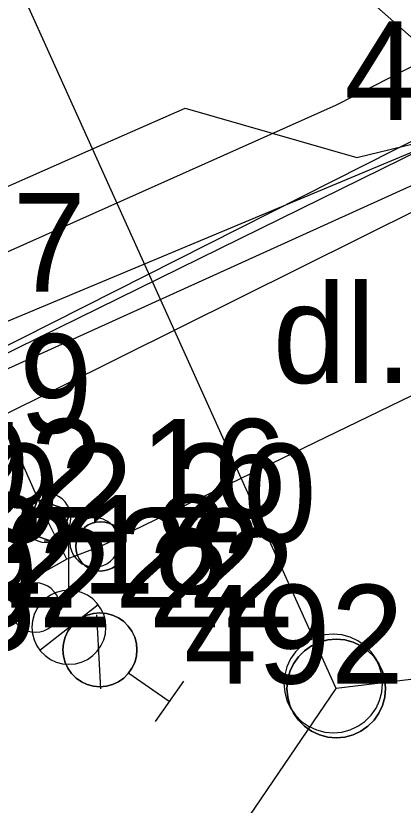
# Model space of a CAD drawing. Extents: x -695326 to -694942, y -1122979 to -1122738.
# Drawn here: x -694975.72 to -694971.79, y -1122884 to -1122876 of the extents above; entities that cross this region are included whole.
import ezdxf

# ---------------------------------------------------------------- set-up
doc = ezdxf.new("R2010")
doc.units = 0
for name, color, linetype in [('Level 29', 7, 'Continuous'), ('Level 30', 7, 'Continuous'), ('Level 35', 7, 'Continuous'), ('Level 36', 7, 'Continuous'), ('Level 37', 7, 'Continuous'), ('Level 38', 7, 'Continuous'), ('Level 44', 7, 'Continuous'), ('Level 51', 7, 'Continuous'), ('Level 53', 7, 'Continuous'), ('Popisy', 7, 'Continuous'), ('Rozhraní ploch', 7, 'Continuous'), ('trasa_man_Mesto', 7, 'Continuous')]:
    doc.layers.add(name, color=color, linetype=linetype)

msp = doc.modelspace()

# ---------------------------------------------------------------- linework, layer by layer
at = {"layer": 'Level 29'}
for p, q in [((-694975.41, -1122881.09), (-694975.41, -1122881.09)), ((-694974.92, -1122881.34), (-694974.92, -1122881.34)), ((-694975.52, -1122882), (-694975.52, -1122882)), ((-694975.18, -1122882.2), (-694975.18, -1122882.2))]:
    msp.add_line(p, q, dxfattribs=at)
for points in [[(-694975.16, -1122881.09), (-694975.1638, -1122881.0466), (-694975.1751, -1122881.0045), (-694975.1935, -1122880.965), (-694975.2185, -1122880.9293), (-694975.2493, -1122880.8985), (-694975.285, -1122880.8735), (-694975.3245, -1122880.8551), (-694975.3666, -1122880.8438), (-694975.41, -1122880.84), (-694975.4534, -1122880.8438), (-694975.4955, -1122880.8551), (-694975.535, -1122880.8735), (-694975.5707, -1122880.8985), (-694975.6015, -1122880.9293), (-694975.6265, -1122880.965), (-694975.6449, -1122881.0045), (-694975.6562, -1122881.0466), (-694975.66, -1122881.09), (-694975.6562, -1122881.1334), (-694975.6449, -1122881.1755), (-694975.6265, -1122881.215), (-694975.6015, -1122881.2507), (-694975.5707, -1122881.2815), (-694975.535, -1122881.3065), (-694975.4955, -1122881.3249), (-694975.4534, -1122881.3362), (-694975.41, -1122881.34), (-694975.3666, -1122881.3362), (-694975.3245, -1122881.3249), (-694975.285, -1122881.3065), (-694975.2493, -1122881.2815), (-694975.2185, -1122881.2507), (-694975.1935, -1122881.215), (-694975.1751, -1122881.1755), (-694975.1638, -1122881.1334), (-694975.16, -1122881.09)], [(-694974.67, -1122881.34), (-694974.6738, -1122881.2966), (-694974.6851, -1122881.2545), (-694974.7035, -1122881.215), (-694974.7285, -1122881.1793), (-694974.7593, -1122881.1485), (-694974.795, -1122881.1235), (-694974.8345, -1122881.1051), (-694974.8766, -1122881.0938), (-694974.92, -1122881.09), (-694974.9634, -1122881.0938), (-694975.0055, -1122881.1051), (-694975.045, -1122881.1235), (-694975.0807, -1122881.1485), (-694975.1115, -1122881.1793), (-694975.1365, -1122881.215), (-694975.1549, -1122881.2545), (-694975.1662, -1122881.2966), (-694975.17, -1122881.34), (-694975.1662, -1122881.3834), (-694975.1549, -1122881.4255), (-694975.1365, -1122881.465), (-694975.1115, -1122881.5007), (-694975.0807, -1122881.5315), (-694975.045, -1122881.5565), (-694975.0055, -1122881.5749), (-694974.9634, -1122881.5862), (-694974.92, -1122881.59), (-694974.8766, -1122881.5862), (-694974.8345, -1122881.5749), (-694974.795, -1122881.5565), (-694974.7593, -1122881.5315), (-694974.7285, -1122881.5007), (-694974.7035, -1122881.465), (-694974.6851, -1122881.4255), (-694974.6738, -1122881.3834), (-694974.67, -1122881.34)], [(-694975.43, -1122881.325), (-694974.93, -1122881.325)], [(-694975.18, -1122881.825), (-694975.18, -1122881.325)], [(-694975.27, -1122882), (-694975.2738, -1122881.9566), (-694975.2851, -1122881.9145), (-694975.3035, -1122881.875), (-694975.3285, -1122881.8393), (-694975.3593, -1122881.8085), (-694975.395, -1122881.7835), (-694975.4345, -1122881.7651), (-694975.4766, -1122881.7538), (-694975.52, -1122881.75), (-694975.5634, -1122881.7538), (-694975.6055, -1122881.7651), (-694975.645, -1122881.7835), (-694975.6807, -1122881.8085), (-694975.7115, -1122881.8393), (-694975.7365, -1122881.875)], [(-694974.805, -1122882.2), (-694974.8107, -1122882.1349), (-694974.8276, -1122882.0717), (-694974.8552, -1122882.0125), (-694974.8927, -1122881.959), (-694974.939, -1122881.9127), (-694974.9925, -1122881.8752), (-694975.0517, -1122881.8476), (-694975.1149, -1122881.8307), (-694975.18, -1122881.825), (-694975.2451, -1122881.8307), (-694975.3083, -1122881.8476), (-694975.3675, -1122881.8752), (-694975.421, -1122881.9127), (-694975.4673, -1122881.959), (-694975.5048, -1122882.0125), (-694975.5324, -1122882.0717), (-694975.5493, -1122882.1349), (-694975.555, -1122882.2), (-694975.5493, -1122882.2651), (-694975.5324, -1122882.3283), (-694975.5048, -1122882.3875), (-694975.4673, -1122882.441), (-694975.421, -1122882.4873), (-694975.3675, -1122882.5248), (-694975.3083, -1122882.5524), (-694975.2451, -1122882.5693), (-694975.18, -1122882.575), (-694975.1149, -1122882.5693), (-694975.0517, -1122882.5524), (-694974.9925, -1122882.5248), (-694974.939, -1122882.4873), (-694974.8927, -1122882.441), (-694974.8552, -1122882.3875), (-694974.8276, -1122882.3283), (-694974.8107, -1122882.2651), (-694974.805, -1122882.2)], [(-694975.7365, -1122882.125), (-694975.7115, -1122882.1607), (-694975.6807, -1122882.1915), (-694975.645, -1122882.2165), (-694975.6055, -1122882.2349), (-694975.5634, -1122882.2462), (-694975.52, -1122882.25), (-694975.4766, -1122882.2462), (-694975.4345, -1122882.2349), (-694975.395, -1122882.2165), (-694975.3593, -1122882.1915), (-694975.3285, -1122882.1607), (-694975.3035, -1122882.125), (-694975.2851, -1122882.0855), (-694975.2738, -1122882.0434), (-694975.27, -1122882)], [(-694975.474, -1122882.431), (-694974.884, -1122881.968)]]:
    msp.add_lwpolyline(points, dxfattribs=at)
at = {"layer": 'Level 30'}
msp.add_line((-694972.5, -1122882.77), (-694972.5, -1122882.77), dxfattribs=at)
msp.add_lwpolyline([(-694972, -1122882.77), (-694972.0076, -1122882.6832), (-694972.0302, -1122882.599), (-694972.067, -1122882.52), (-694972.117, -1122882.4486), (-694972.1786, -1122882.387), (-694972.25, -1122882.337), (-694972.329, -1122882.3002), (-694972.4132, -1122882.2776), (-694972.5, -1122882.27), (-694972.5868, -1122882.2776), (-694972.671, -1122882.3002), (-694972.75, -1122882.337), (-694972.8214, -1122882.387), (-694972.883, -1122882.4486), (-694972.933, -1122882.52), (-694972.9698, -1122882.599), (-694972.9924, -1122882.6832), (-694973, -1122882.77), (-694972.9924, -1122882.8568), (-694972.9698, -1122882.941), (-694972.933, -1122883.02), (-694972.883, -1122883.0914), (-694972.8214, -1122883.153), (-694972.75, -1122883.203), (-694972.671, -1122883.2398), (-694972.5868, -1122883.2624), (-694972.5, -1122883.27), (-694972.4132, -1122883.2624), (-694972.329, -1122883.2398), (-694972.25, -1122883.203), (-694972.1786, -1122883.153), (-694972.117, -1122883.0914), (-694972.067, -1122883.02), (-694972.0302, -1122882.941), (-694972.0076, -1122882.8568), (-694972, -1122882.77)], dxfattribs=at)
at = {"layer": 'Level 35'}
msp.add_lwpolyline([(-695131.2467, -1122978.8639), (-695132.65, -1122975.94), (-695157.61, -1122969.63), (-695140.47, -1122958.8), (-695136.63, -1122948.53), (-695119.01, -1122943.49), (-695100.79, -1122937.97), (-695082.69, -1122932.49), (-695067.48, -1122925.68), (-695054.28, -1122919.15), (-695039.04, -1122911.54), (-695024.78, -1122904.45), (-695010.56, -1122897.35), (-694996.02, -1122890.13), (-694983.12, -1122883.66), (-694965.65, -1122874.99), (-694952.69, -1122868.61), (-694948.6266, -1122866.5863)], dxfattribs=at)
at = {"layer": 'Level 36'}
for p, q in [((-694960.69, -1122874.53), (-694974.86, -1122881.38)), ((-694975.2, -1122881.51), (-694975.39, -1122881.13)), ((-694974.86, -1122881.38), (-694975.2, -1122881.51))]:
    msp.add_line(p, q, dxfattribs=at)
for points in [[(-694975.39, -1122881.13), (-694982.04, -1122866.09), (-694989.57, -1122849.4), (-694995.06, -1122837.58), (-694995.98, -1122835.83), (-695003.87, -1122820.22)], [(-694976.036, -1122879.197), (-694976, -1122879.18), (-694970.42, -1122876.85), (-694965.1, -1122874.36)], [(-694971.19, -1122876.26), (-694972.47, -1122876.91), (-694977.58, -1122879.19), (-694981.14, -1122881.07), (-694984.99, -1122882.65), (-695001.8, -1122890.18)], [(-694999.83, -1122891.63), (-694989.59, -1122886.52), (-694978.72, -1122881.18), (-694978.15, -1122880.08), (-694977.9, -1122878.66), (-694974.84, -1122877.31), (-694974, -1122876.94), (-694972.26, -1122877.44), (-694970.98, -1122877.13)], [(-694975.2, -1122881.51), (-694975.61, -1122881.74), (-694975.99, -1122881.91)]]:
    msp.add_lwpolyline(points, dxfattribs=at)
at = {"layer": 'Level 37'}
msp.add_lwpolyline([(-695018.76, -1122900.99), (-694999.77, -1122890.98), (-694996.09, -1122889.21), (-694986.68, -1122884.5), (-694984.84, -1122883.53), (-694978.51, -1122880.71), (-694968.71, -1122875.76), (-694963.71, -1122872.9), (-694961.76, -1122871.96), (-694957.17, -1122869.93), (-694955.67, -1122868.8), (-694948.6716, -1122865.3476)], dxfattribs=at)
at = {"layer": 'Level 38'}
for p, q in [((-694972.47, -1122882.82), (-694981.23, -1122863.43)), ((-694959.99, -1122881.29), (-694972.47, -1122882.82)), ((-694974.82, -1122886.27), (-694972.47, -1122882.82))]:
    msp.add_line(p, q, dxfattribs=at)
at = {"layer": 'Level 44'}
for p, q in [((-694975.39, -1122881.13), (-694975.39, -1122881.13)), ((-694974.86, -1122881.38), (-694974.86, -1122881.38)), ((-694975.17, -1122882.23), (-694975.17, -1122882.23)), ((-694972.47, -1122882.82), (-694972.47, -1122882.82))]:
    msp.add_line(p, q, dxfattribs=at)
for points in [[(-694975.2804, -1122881.3547), (-694975.1653, -1122881.0204), (-694975.4996, -1122880.9053), (-694975.6147, -1122881.2396), (-694975.2804, -1122881.3547)], [(-694974.61, -1122881.38), (-694974.6138, -1122881.3366), (-694974.6251, -1122881.2945), (-694974.6435, -1122881.255), (-694974.6685, -1122881.2193), (-694974.6993, -1122881.1885), (-694974.735, -1122881.1635), (-694974.7745, -1122881.1451), (-694974.8166, -1122881.1338), (-694974.86, -1122881.13), (-694974.9034, -1122881.1338), (-694974.9455, -1122881.1451), (-694974.985, -1122881.1635), (-694975.0207, -1122881.1885), (-694975.0515, -1122881.2193), (-694975.0765, -1122881.255), (-694975.0949, -1122881.2945), (-694975.1062, -1122881.3366), (-694975.11, -1122881.38), (-694975.1062, -1122881.4234), (-694975.0949, -1122881.4655), (-694975.0765, -1122881.505), (-694975.0515, -1122881.5407), (-694975.0207, -1122881.5715), (-694974.985, -1122881.5965), (-694974.9455, -1122881.6149), (-694974.9034, -1122881.6262), (-694974.86, -1122881.63), (-694974.8166, -1122881.6262), (-694974.7745, -1122881.6149), (-694974.735, -1122881.5965), (-694974.6993, -1122881.5715), (-694974.6685, -1122881.5407), (-694974.6435, -1122881.505), (-694974.6251, -1122881.4655), (-694974.6138, -1122881.4234), (-694974.61, -1122881.38)], [(-694974.4905, -1122882.428), (-694974.4962, -1122882.3629), (-694974.5131, -1122882.2997), (-694974.5407, -1122882.2405), (-694974.5782, -1122882.1869), (-694974.6244, -1122882.1407), (-694974.678, -1122882.1032), (-694974.7372, -1122882.0756), (-694974.8004, -1122882.0587), (-694974.8655, -1122882.053), (-694974.9306, -1122882.0587), (-694974.9937, -1122882.0756), (-694975.053, -1122882.1032), (-694975.1065, -1122882.1407), (-694975.1527, -1122882.1869), (-694975.1902, -1122882.2405), (-694975.2179, -1122882.2997), (-694975.2348, -1122882.3629), (-694975.2405, -1122882.428), (-694975.2348, -1122882.4931), (-694975.2179, -1122882.5562), (-694975.1902, -1122882.6155), (-694975.1527, -1122882.669), (-694975.1065, -1122882.7152), (-694975.053, -1122882.7527), (-694974.9937, -1122882.7804), (-694974.9306, -1122882.7973), (-694974.8655, -1122882.803), (-694974.8004, -1122882.7973), (-694974.7372, -1122882.7804), (-694974.678, -1122882.7527), (-694974.6244, -1122882.7152), (-694974.5782, -1122882.669), (-694974.5407, -1122882.6155), (-694974.5131, -1122882.5562), (-694974.4962, -1122882.4931), (-694974.4905, -1122882.428)], [(-694974.9, -1122882.075), (-694974.86, -1122882.824)], [(-694971.97, -1122882.82), (-694971.9776, -1122882.7332), (-694972.0002, -1122882.649), (-694972.037, -1122882.57), (-694972.087, -1122882.4986), (-694972.1486, -1122882.437), (-694972.22, -1122882.387), (-694972.299, -1122882.3502), (-694972.3832, -1122882.3276), (-694972.47, -1122882.32), (-694972.5568, -1122882.3276), (-694972.641, -1122882.3502), (-694972.72, -1122882.387), (-694972.7914, -1122882.437), (-694972.853, -1122882.4986), (-694972.903, -1122882.57), (-694972.9398, -1122882.649), (-694972.9624, -1122882.7332), (-694972.97, -1122882.82), (-694972.9624, -1122882.9068), (-694972.9398, -1122882.991), (-694972.903, -1122883.07), (-694972.853, -1122883.1414), (-694972.7914, -1122883.203), (-694972.72, -1122883.253), (-694972.641, -1122883.2898), (-694972.5568, -1122883.3124), (-694972.47, -1122883.32), (-694972.3832, -1122883.3124), (-694972.299, -1122883.2898), (-694972.22, -1122883.253), (-694972.1486, -1122883.203), (-694972.087, -1122883.1414), (-694972.037, -1122883.07), (-694972.0002, -1122882.991), (-694971.9776, -1122882.9068), (-694971.97, -1122882.82)], [(-694974.573, -1122882.664), (-694974.163, -1122882.95)], [(-694974.02, -1122882.746), (-694974.306, -1122883.155)]]:
    msp.add_lwpolyline(points, dxfattribs=at)
for points in [[(-694975.1653, -1122881.0204), (-694975.2804, -1122881.3547), (-694975.6147, -1122881.2396), (-694975.4996, -1122880.9053)], [(-694974.8166, -1122881.6262), (-694974.86, -1122881.63), (-694974.9034, -1122881.6262), (-694974.9455, -1122881.6149), (-694974.985, -1122881.5965), (-694975.0207, -1122881.5715), (-694975.0515, -1122881.5407), (-694975.0765, -1122881.505), (-694975.0949, -1122881.4655), (-694975.1062, -1122881.4234), (-694975.11, -1122881.38), (-694975.1062, -1122881.3366), (-694975.0949, -1122881.2945), (-694975.0765, -1122881.255), (-694975.0515, -1122881.2193), (-694975.0207, -1122881.1885), (-694974.985, -1122881.1635), (-694974.9455, -1122881.1451), (-694974.9034, -1122881.1338), (-694974.86, -1122881.13), (-694974.8166, -1122881.1338), (-694974.7745, -1122881.1451), (-694974.735, -1122881.1635), (-694974.6993, -1122881.1885), (-694974.6685, -1122881.2193), (-694974.6435, -1122881.255), (-694974.6251, -1122881.2945), (-694974.6138, -1122881.3366), (-694974.61, -1122881.38), (-694974.6138, -1122881.4234), (-694974.6251, -1122881.4655), (-694974.6435, -1122881.505), (-694974.6685, -1122881.5407), (-694974.6993, -1122881.5715), (-694974.735, -1122881.5965), (-694974.7745, -1122881.6149)], [(-694974.8004, -1122882.7973), (-694974.8655, -1122882.803), (-694974.9306, -1122882.7973), (-694974.9937, -1122882.7804), (-694975.053, -1122882.7527), (-694975.1065, -1122882.7152), (-694975.1527, -1122882.669), (-694975.1902, -1122882.6155), (-694975.2179, -1122882.5562), (-694975.2348, -1122882.4931), (-694975.2405, -1122882.428), (-694975.2348, -1122882.3629), (-694975.2179, -1122882.2997), (-694975.1902, -1122882.2405), (-694975.1527, -1122882.1869), (-694975.1065, -1122882.1407), (-694975.053, -1122882.1032), (-694974.9937, -1122882.0756), (-694974.9306, -1122882.0587), (-694974.8655, -1122882.053), (-694974.8004, -1122882.0587), (-694974.7372, -1122882.0756), (-694974.678, -1122882.1032), (-694974.6244, -1122882.1407), (-694974.5782, -1122882.1869), (-694974.5407, -1122882.2405), (-694974.5131, -1122882.2997), (-694974.4962, -1122882.3629), (-694974.4905, -1122882.428), (-694974.4962, -1122882.4931), (-694974.5131, -1122882.5562), (-694974.5407, -1122882.6155), (-694974.5782, -1122882.669), (-694974.6244, -1122882.7152), (-694974.678, -1122882.7527), (-694974.7372, -1122882.7804)], [(-694972.3832, -1122883.3124), (-694972.47, -1122883.32), (-694972.5568, -1122883.3124), (-694972.641, -1122883.2898), (-694972.72, -1122883.253), (-694972.7914, -1122883.203), (-694972.853, -1122883.1414), (-694972.903, -1122883.07), (-694972.9398, -1122882.991), (-694972.9624, -1122882.9068), (-694972.97, -1122882.82), (-694972.9624, -1122882.7332), (-694972.9398, -1122882.649), (-694972.903, -1122882.57), (-694972.853, -1122882.4986), (-694972.7914, -1122882.437), (-694972.72, -1122882.387), (-694972.641, -1122882.3502), (-694972.5568, -1122882.3276), (-694972.47, -1122882.32), (-694972.3832, -1122882.3276), (-694972.299, -1122882.3502), (-694972.22, -1122882.387), (-694972.1486, -1122882.437), (-694972.087, -1122882.4986), (-694972.037, -1122882.57), (-694972.0002, -1122882.649), (-694971.9776, -1122882.7332), (-694971.97, -1122882.82), (-694971.9776, -1122882.9068), (-694972.0002, -1122882.991), (-694972.037, -1122883.07), (-694972.087, -1122883.1414), (-694972.1486, -1122883.203), (-694972.22, -1122883.253), (-694972.299, -1122883.2898)]]:
    msp.add_lwpolyline(points, close=True, dxfattribs=at)
at = {"layer": 'Level 51'}
for p, q in [((-694975.41, -1122881.09), (-694975.41, -1122881.09)), ((-694974.92, -1122881.34), (-694974.92, -1122881.34)), ((-694975.52, -1122882), (-694975.52, -1122882)), ((-694975.18, -1122882.2), (-694975.18, -1122882.2)), ((-694972.5, -1122882.77), (-694972.5, -1122882.77))]:
    msp.add_line(p, q, dxfattribs=at)
at = {"layer": 'Level 53'}
msp.add_line((-694971.65, -1122877.7), (-694977.65, -1122880.42), dxfattribs=at)
at = {"layer": 'Rozhraní ploch'}
msp.add_lwpolyline([(-694948.6057, -1122867.1627), (-694956.13, -1122870.93), (-694968.24, -1122876.97), (-694970.76, -1122877.06), (-694972.49, -1122875.53), (-694988.7, -1122840.9), (-694989.99, -1122837.35), (-694995.04, -1122824.65), (-694994.46, -1122821.21), (-694991.3, -1122815.99), (-694987.37, -1122813.69)], dxfattribs=at)
at = {"layer": 'trasa_man_Mesto'}
msp.add_lwpolyline([(-695115.2906, -1122889.8517), (-695108.3885, -1122910.0791), (-695087.6818, -1122902.41), (-695080.2044, -1122924.5546), (-695073.8297, -1122926.6613), (-695067.9357, -1122924.1284), (-695054.6143, -1122918.3781), (-695050.8425, -1122916.2424), (-695049.1379, -1122915.3798), (-695038.0755, -1122910.1636), (-695019.5172, -1122901.4149), (-695011.8093, -1122897.3829), (-694997.1325, -1122889.7296), (-694994.7913, -1122888.5316), (-694986.4398, -1122884.3217), (-694976.2194, -1122879.6257), (-694968.5661, -1122875.8606), (-694963.5894, -1122873.0197), (-694957.0792, -1122869.8844), (-694955.7239, -1122868.9261), (-694953.7798, -1122867.954), (-694950.0421, -1122866.1194), (-694948.6681, -1122865.4458)], dxfattribs=at)

# ---------------------------------------------------------------- texts
at = {"layer": 'Level 53'}
for s, p in [('492 17', (-694972.387, -1122877.06)), ('492 17', (-694979.097, -1122878.8)), ('492 19', (-694979.031, -1122880.23)), ('492 16', (-694977.064, -1122881.09)), ('492 20', (-694976.76, -1122881.34)), ('492 18', (-694977.657, -1122881.86)), ('492 22', (-694977.318, -1122882)), ('492 22', (-694976.978, -1122882.2)), ('492 15', (-694979.607, -1122882.44)), ('492 31', (-694974.014, -1122882.77))]:
    msp.add_text(s, height=1, dxfattribs=at).set_placement(p)
at = {"layer": 'Popisy'}
msp.add_text('dl.', height=1, dxfattribs=at).set_placement((-694973.114, -1122879.725))

doc.saveas('drawing.dxf')
